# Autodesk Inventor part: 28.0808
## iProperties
Created: 2009-01
Part Number: 28.0808
Document SubType Name: Modeling
Designer: Administrator
Density: 2.71 g/cm^3
Material: Aluminum-6061
Mass: 34.5471 g
Surface Area: 46.8656 cm^2
Volume: 12.748 cm^3
Description: SHAFT FASTENER RIGHT LR 16
Author: Administrator
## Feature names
1. Base1
